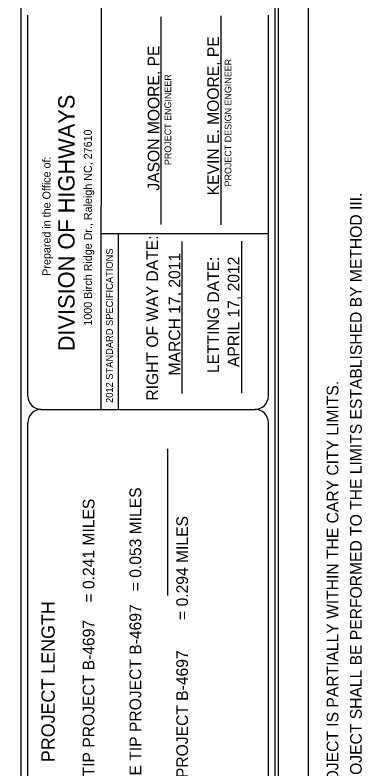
# Model space of a CAD drawing. Extents: x 2026893 to 2039781, y 729195 to 739590.
# Drawn here: x 2029974 to 2030883, y 736122 to 738095 of the extents above; entities that cross this region are included whole.
import ezdxf

# ---------------------------------------------------------------- set-up
doc = ezdxf.new("R2010")
doc.units = 0
for name, color, linetype in [('Default', 7, 'Continuous'), ('Sheet Cutting Line CELL', 7, 'Continuous'), ('Sheet Data Field CELL', 7, 'Continuous'), ('Sheet Plot Border Inside CELL', 7, 'Continuous'), ('Sheet Plot Border Outside CELL', 7, 'Continuous'), ('Sheet Title CELL', 7, 'Continuous')]:
    doc.layers.add(name, color=color, linetype=linetype)

msp = doc.modelspace()

# ---------------------------------------------------------------- linework, layer by layer
at = {"layer": 'Default'}
msp.add_line((2030374.8, 736576), (2030374.8, 736959.3), dxfattribs=at)
at = {"layer": 'Sheet Cutting Line CELL'}
msp.add_line((2030742.8, 733695.9), (2030742.8, 739589.9), dxfattribs=at)
at = {"layer": 'Sheet Plot Border Inside CELL'}
msp.add_lwpolyline([(2030664.3, 733741.4), (2030664.3, 739574.2), (2026971.4, 739574.2), (2026971.4, 733741.4)], close=True, dxfattribs=at)
at = {"layer": 'Sheet Plot Border Outside CELL'}
msp.add_lwpolyline([(2026892.9, 739589.9), (2026892.9, 733695.9), (2030742.8, 733695.9), (2030742.8, 739589.9)], close=True, dxfattribs=at)
at = {"layer": 'Sheet Title CELL'}
for p, q in [((2029990.3, 734507.9), (2029990.3, 739477.9)), ((2030199.5, 738130.4), (2030199.4, 737062.9)), ((2030007.8, 737097.9), (2030007.8, 738095.4)), ((2030356.9, 737547.5), (2030357, 738090.5)), ((2030514.4, 737546.3), (2030514.4, 738093.2)), ((2030199.4, 737523.4), (2030637.8, 737523.4)), ((2030244.1, 737523.4), (2030244.1, 737062.9)), ((2030411.5, 737502.4), (2030411.5, 737104.2)), ((2030567.6, 737503.8), (2030567.6, 737105.6)), ((2030244.1, 737390.7), (2030244.1, 737390.7)), ((2030411.6, 737303.2), (2030411.6, 737303.2)), ((2030042.8, 737062.9), (2030602.8, 737062.9)), ((2030007.9, 735697.9), (2030007.9, 737027.9))]:
    msp.add_line(p, q, dxfattribs=at)
for points in [[(2030655.4, 734315.4), (2030655.4, 739495.4)], [(2030637.8, 737097.9), (2030637.9, 738095.4)], [(2030637.9, 735697.9), (2030637.9, 737027.9)]]:
    msp.add_lwpolyline(points, dxfattribs=at)
for centre, start, end in [((2030042.7, 737098), 180, 270), ((2030602.7, 737098), 270, 360), ((2030042.7, 737028), 90, 180), ((2030602.7, 737028), 360, 90)]:
    msp.add_arc(centre, 35, start, end, dxfattribs=at)

# ---------------------------------------------------------------- texts
at = {"layer": 'Default'}
for s, p in [('CLEARING ON THIS PROJECT SHALL BE PERFORMED TO THE LIMITS ESTABLISHED BY METHOD III.', (2030882.2, 735650.8)), ('THIS PROJECT IS PARTIALLY WITHIN THE CARY CITY LIMITS.', (2030821, 735924.8)), ('LENGTH STRUCTURE TIP PROJECT B-4697   = 0.053 MILES', (2030304.7, 735701.5)), ('LENGTH ROADWAY TIP PROJECT B-4697    = 0.241 MILES', (2030182.2, 735701.5)), ('TOTAL LENGTH TIP PROJECT B-4697       = 0.294 MILES', (2030427.2, 735701.5))]:
    msp.add_text(s, height=30.625, rotation=90, dxfattribs=at).set_placement(p)
at = {"layer": 'Sheet Data Field CELL'}
for s, p in [('KEVIN E. MOORE, PE', (2030508.3, 737623.5)), ('JASON MOORE, PE', (2030352.4, 737635.6)), ('MARCH 17, 2011', (2030407.1, 737151.8)), ('APRIL 17, 2012', (2030561.7, 737173.8))]:
    msp.add_text(s, height=30.625, rotation=90, dxfattribs=at).set_placement(p)
at = {"layer": 'Sheet Title CELL'}
for s, height, p in [('PROJECT DESIGN ENGINEER', 17.498, (2030540.9, 737646.7)), ('PROJECT ENGINEER', 17.498, (2030383.2, 737702.7)), ('DIVISION OF HIGHWAYS', 42.655, (2030130.1, 737215.1)), ('1000 Birch Ridge Dr., Raleigh NC, 27610', 21, (2030175.5, 737282.3)), ('Prepared in the Office of:', 20.998, (2030067.2, 737412.9)), ('RIGHT OF WAY DATE: ', 30.624, (2030348.9, 737085.9)), ('2012 STANDARD SPECIFICATIONS', 18.2, (2030230.6, 737079.9)), ('LETTING DATE:', 30.624, (2030508.7, 737158.1)), ('PROJECT LENGTH', 34.999, (2030078.3, 736139.3))]:
    msp.add_text(s, height=height, rotation=90, dxfattribs=at).set_placement(p)

doc.saveas('drawing.dxf')
